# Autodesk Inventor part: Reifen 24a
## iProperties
Shininess: 64.0
Length Units: 11269
Angle Units: 11279
Time Units: 11290
Mass Units: 11283
Length Display Precision: 3
Angle Display Precision: 2
Compacted: True
Part Number: Reifen 24a
Document SubType Name: Modeling
Created: 2003-10
Designer: Bernhard Fetzer
Manufacturer: Standard
Standards Organization: Custom
Material: Silicone
Density: 1 g/cm^3
Density: 0.0
Volumn: 0.0
Area: 0.0
PropertySet Name: Model Information
Control State: 0
Master: False
Checked Out: False
Author: Bernhard Fetzer
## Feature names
1. Revolution1
2. Extrusion1
3. Mirror1
4. Circular Pattern1
5. Revolution2
